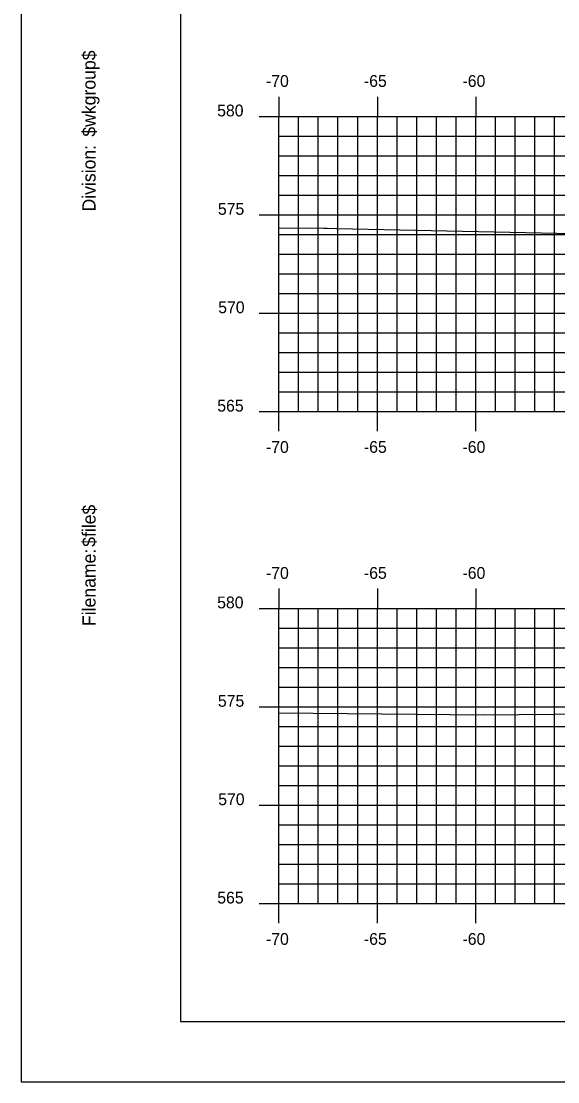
# Model space of a CAD drawing. Extents: x 1048109 to 1048279, y 781630 to 781740.
# Drawn here: x 1048108.6 to 1048135.9, y 781630.1 to 781684 of the extents above; entities that cross this region are included whole.
import ezdxf

# ---------------------------------------------------------------- set-up
doc = ezdxf.new("R2010")
doc.units = 0
for name, color, linetype in [('Default', 7, 'Continuous'), ('H_V ANNOTATION', 7, 'Continuous'), ('MAJOR', 7, 'Continuous'), ('MINOR', 7, 'Continuous'), ('S_Roadway_Centerline', 7, 'Continuous')]:
    doc.layers.add(name, color=color, linetype=linetype)

msp = doc.modelspace()

# ---------------------------------------------------------------- linework, layer by layer
at = {"layer": 'Default'}
for p, q in [((1048116.734, 781738.195), (1048116.734, 781633.195)), ((1048116.734, 781633.195), (1048276.734, 781633.195))]:
    msp.add_line(p, q, dxfattribs=at)
msp.add_lwpolyline([(1048108.64, 781630.136), (1048278.64, 781630.136), (1048278.64, 781740.136), (1048108.64, 781740.136)], close=True, dxfattribs=at)
at = {"layer": 'MAJOR'}
for p, q in [((1048121.733, 781680.197), (1048121.733, 781679.195)), ((1048121.733, 781680.197), (1048121.733, 781679.195)), ((1048126.733, 781680.197), (1048126.733, 781679.195)), ((1048126.733, 781680.197), (1048126.733, 781679.195)), ((1048131.733, 781680.197), (1048131.733, 781679.195)), ((1048131.733, 781680.197), (1048131.733, 781679.195)), ((1048120.731, 781679.195), (1048121.733, 781679.195)), ((1048120.731, 781679.195), (1048121.733, 781679.195)), ((1048121.733, 781679.195), (1048261.733, 781679.195)), ((1048121.733, 781664.195), (1048121.733, 781679.195)), ((1048121.733, 781664.195), (1048121.733, 781679.195)), ((1048121.733, 781679.195), (1048261.733, 781679.195)), ((1048121.733, 781679.195), (1048261.733, 781679.195)), ((1048121.733, 781664.195), (1048121.733, 781679.195)), ((1048121.733, 781664.195), (1048121.733, 781679.195)), ((1048121.733, 781679.195), (1048261.733, 781679.195)), ((1048126.733, 781664.195), (1048126.733, 781679.195)), ((1048126.733, 781664.195), (1048126.733, 781679.195)), ((1048131.733, 781664.195), (1048131.733, 781679.195)), ((1048131.733, 781664.195), (1048131.733, 781679.195)), ((1048120.731, 781674.195), (1048121.733, 781674.195)), ((1048120.731, 781674.195), (1048121.733, 781674.195)), ((1048121.733, 781674.195), (1048261.733, 781674.195)), ((1048121.733, 781674.195), (1048261.733, 781674.195)), ((1048120.731, 781669.195), (1048121.733, 781669.195)), ((1048120.731, 781669.195), (1048121.733, 781669.195)), ((1048121.733, 781669.195), (1048261.733, 781669.195)), ((1048121.733, 781669.195), (1048261.733, 781669.195)), ((1048120.731, 781664.195), (1048121.733, 781664.195)), ((1048120.731, 781664.195), (1048121.733, 781664.195)), ((1048121.733, 781664.195), (1048261.733, 781664.195)), ((1048121.733, 781664.195), (1048261.733, 781664.195)), ((1048121.733, 781663.193), (1048121.733, 781664.195)), ((1048121.733, 781664.195), (1048261.733, 781664.195)), ((1048121.733, 781664.195), (1048261.733, 781664.195)), ((1048121.733, 781663.193), (1048121.733, 781664.195)), ((1048126.733, 781663.193), (1048126.733, 781664.195)), ((1048126.733, 781663.193), (1048126.733, 781664.195)), ((1048131.733, 781663.193), (1048131.733, 781664.195)), ((1048131.733, 781663.193), (1048131.733, 781664.195)), ((1048121.733, 781655.197), (1048121.733, 781654.195)), ((1048121.733, 781655.197), (1048121.733, 781654.195)), ((1048126.733, 781655.197), (1048126.733, 781654.195)), ((1048126.733, 781655.197), (1048126.733, 781654.195)), ((1048131.733, 781655.197), (1048131.733, 781654.195)), ((1048131.733, 781655.197), (1048131.733, 781654.195)), ((1048120.731, 781654.195), (1048121.733, 781654.195)), ((1048120.731, 781654.195), (1048121.733, 781654.195)), ((1048121.733, 781654.195), (1048261.733, 781654.195)), ((1048121.733, 781639.195), (1048121.733, 781654.195)), ((1048121.733, 781639.195), (1048121.733, 781654.195)), ((1048121.733, 781654.195), (1048261.733, 781654.195)), ((1048121.733, 781654.195), (1048261.733, 781654.195)), ((1048121.733, 781639.195), (1048121.733, 781654.195)), ((1048121.733, 781639.195), (1048121.733, 781654.195)), ((1048121.733, 781654.195), (1048261.733, 781654.195)), ((1048126.733, 781639.195), (1048126.733, 781654.195)), ((1048126.733, 781639.195), (1048126.733, 781654.195)), ((1048131.733, 781639.195), (1048131.733, 781654.195)), ((1048131.733, 781639.195), (1048131.733, 781654.195)), ((1048120.731, 781649.195), (1048121.733, 781649.195)), ((1048120.731, 781649.195), (1048121.733, 781649.195)), ((1048121.733, 781649.195), (1048261.733, 781649.195)), ((1048121.733, 781649.195), (1048261.733, 781649.195)), ((1048120.731, 781644.195), (1048121.733, 781644.195)), ((1048120.731, 781644.195), (1048121.733, 781644.195)), ((1048121.733, 781644.195), (1048261.733, 781644.195)), ((1048121.733, 781644.195), (1048261.733, 781644.195)), ((1048120.731, 781639.195), (1048121.733, 781639.195)), ((1048120.731, 781639.195), (1048121.733, 781639.195)), ((1048121.733, 781639.195), (1048261.733, 781639.195)), ((1048121.733, 781639.195), (1048261.733, 781639.195)), ((1048121.733, 781638.193), (1048121.733, 781639.195)), ((1048121.733, 781639.195), (1048261.733, 781639.195)), ((1048121.733, 781639.195), (1048261.733, 781639.195)), ((1048121.733, 781638.193), (1048121.733, 781639.195)), ((1048126.733, 781638.193), (1048126.733, 781639.195)), ((1048126.733, 781638.193), (1048126.733, 781639.195)), ((1048131.733, 781638.193), (1048131.733, 781639.195)), ((1048131.733, 781638.193), (1048131.733, 781639.195))]:
    msp.add_line(p, q, dxfattribs=at)
at = {"layer": 'MINOR'}
for p, q in [((1048122.733, 781664.195), (1048122.733, 781679.195)), ((1048122.733, 781664.195), (1048122.733, 781679.195)), ((1048123.733, 781664.195), (1048123.733, 781679.195)), ((1048123.733, 781664.195), (1048123.733, 781679.195)), ((1048124.733, 781664.195), (1048124.733, 781679.195)), ((1048124.733, 781664.195), (1048124.733, 781679.195)), ((1048125.733, 781664.195), (1048125.733, 781679.195)), ((1048125.733, 781664.195), (1048125.733, 781679.195)), ((1048127.733, 781664.195), (1048127.733, 781679.195)), ((1048127.733, 781664.195), (1048127.733, 781679.195)), ((1048128.733, 781664.195), (1048128.733, 781679.195)), ((1048128.733, 781664.195), (1048128.733, 781679.195)), ((1048129.733, 781664.195), (1048129.733, 781679.195)), ((1048129.733, 781664.195), (1048129.733, 781679.195)), ((1048130.733, 781664.195), (1048130.733, 781679.195)), ((1048130.733, 781664.195), (1048130.733, 781679.195)), ((1048132.733, 781664.195), (1048132.733, 781679.195)), ((1048132.733, 781664.195), (1048132.733, 781679.195)), ((1048133.733, 781664.195), (1048133.733, 781679.195)), ((1048133.733, 781664.195), (1048133.733, 781679.195)), ((1048134.733, 781664.195), (1048134.733, 781679.195)), ((1048134.733, 781664.195), (1048134.733, 781679.195)), ((1048135.733, 781664.195), (1048135.733, 781679.195)), ((1048135.733, 781664.195), (1048135.733, 781679.195)), ((1048121.733, 781678.195), (1048261.733, 781678.195)), ((1048121.733, 781678.195), (1048122.735, 781678.195)), ((1048121.733, 781678.195), (1048261.733, 781678.195)), ((1048121.733, 781678.195), (1048122.735, 781678.195)), ((1048121.733, 781677.195), (1048261.733, 781677.195)), ((1048121.733, 781677.195), (1048122.735, 781677.195)), ((1048121.733, 781677.195), (1048261.733, 781677.195)), ((1048121.733, 781677.195), (1048122.735, 781677.195)), ((1048121.733, 781676.195), (1048261.733, 781676.195)), ((1048121.733, 781676.195), (1048122.735, 781676.195)), ((1048121.733, 781676.195), (1048261.733, 781676.195)), ((1048121.733, 781676.195), (1048122.735, 781676.195)), ((1048121.733, 781675.195), (1048261.733, 781675.195)), ((1048121.733, 781675.195), (1048122.735, 781675.195)), ((1048121.733, 781675.195), (1048261.733, 781675.195)), ((1048121.733, 781675.195), (1048122.735, 781675.195)), ((1048121.733, 781673.195), (1048261.733, 781673.195)), ((1048121.733, 781673.195), (1048122.735, 781673.195)), ((1048121.733, 781673.195), (1048261.733, 781673.195)), ((1048121.733, 781673.195), (1048122.735, 781673.195)), ((1048121.733, 781672.195), (1048261.733, 781672.195)), ((1048121.733, 781672.195), (1048122.735, 781672.195)), ((1048121.733, 781672.195), (1048261.733, 781672.195)), ((1048121.733, 781672.195), (1048122.735, 781672.195)), ((1048121.733, 781671.195), (1048261.733, 781671.195)), ((1048121.733, 781671.195), (1048122.735, 781671.195)), ((1048121.733, 781671.195), (1048261.733, 781671.195)), ((1048121.733, 781671.195), (1048122.735, 781671.195)), ((1048121.733, 781670.195), (1048261.733, 781670.195)), ((1048121.733, 781670.195), (1048122.735, 781670.195)), ((1048121.733, 781670.195), (1048261.733, 781670.195)), ((1048121.733, 781670.195), (1048122.735, 781670.195)), ((1048121.733, 781668.195), (1048261.733, 781668.195)), ((1048121.733, 781668.195), (1048122.735, 781668.195)), ((1048121.733, 781668.195), (1048261.733, 781668.195)), ((1048121.733, 781668.195), (1048122.735, 781668.195)), ((1048121.733, 781667.195), (1048261.733, 781667.195)), ((1048121.733, 781667.195), (1048122.735, 781667.195)), ((1048121.733, 781667.195), (1048261.733, 781667.195)), ((1048121.733, 781667.195), (1048122.735, 781667.195)), ((1048121.733, 781666.195), (1048261.733, 781666.195)), ((1048121.733, 781666.195), (1048122.735, 781666.195)), ((1048121.733, 781666.195), (1048261.733, 781666.195)), ((1048121.733, 781666.195), (1048122.735, 781666.195)), ((1048121.733, 781665.195), (1048261.733, 781665.195)), ((1048121.733, 781665.195), (1048122.735, 781665.195)), ((1048121.733, 781665.195), (1048261.733, 781665.195)), ((1048121.733, 781665.195), (1048122.735, 781665.195)), ((1048122.733, 781639.195), (1048122.733, 781654.195)), ((1048122.733, 781639.195), (1048122.733, 781654.195)), ((1048123.733, 781639.195), (1048123.733, 781654.195)), ((1048123.733, 781639.195), (1048123.733, 781654.195)), ((1048124.733, 781639.195), (1048124.733, 781654.195)), ((1048124.733, 781639.195), (1048124.733, 781654.195)), ((1048125.733, 781639.195), (1048125.733, 781654.195)), ((1048125.733, 781639.195), (1048125.733, 781654.195)), ((1048127.733, 781639.195), (1048127.733, 781654.195)), ((1048127.733, 781639.195), (1048127.733, 781654.195)), ((1048128.733, 781639.195), (1048128.733, 781654.195)), ((1048128.733, 781639.195), (1048128.733, 781654.195)), ((1048129.733, 781639.195), (1048129.733, 781654.195)), ((1048129.733, 781639.195), (1048129.733, 781654.195)), ((1048130.733, 781639.195), (1048130.733, 781654.195)), ((1048130.733, 781639.195), (1048130.733, 781654.195)), ((1048132.733, 781639.195), (1048132.733, 781654.195)), ((1048132.733, 781639.195), (1048132.733, 781654.195)), ((1048133.733, 781639.195), (1048133.733, 781654.195)), ((1048133.733, 781639.195), (1048133.733, 781654.195)), ((1048134.733, 781639.195), (1048134.733, 781654.195)), ((1048134.733, 781639.195), (1048134.733, 781654.195)), ((1048135.733, 781639.195), (1048135.733, 781654.195)), ((1048135.733, 781639.195), (1048135.733, 781654.195)), ((1048121.733, 781653.195), (1048261.733, 781653.195)), ((1048121.733, 781653.195), (1048122.735, 781653.195)), ((1048121.733, 781653.195), (1048261.733, 781653.195)), ((1048121.733, 781653.195), (1048122.735, 781653.195)), ((1048121.733, 781652.195), (1048261.733, 781652.195)), ((1048121.733, 781652.195), (1048122.735, 781652.195)), ((1048121.733, 781652.195), (1048261.733, 781652.195)), ((1048121.733, 781652.195), (1048122.735, 781652.195)), ((1048121.733, 781651.195), (1048261.733, 781651.195)), ((1048121.733, 781651.195), (1048122.735, 781651.195)), ((1048121.733, 781651.195), (1048261.733, 781651.195)), ((1048121.733, 781651.195), (1048122.735, 781651.195)), ((1048121.733, 781650.195), (1048261.733, 781650.195)), ((1048121.733, 781650.195), (1048122.735, 781650.195)), ((1048121.733, 781650.195), (1048261.733, 781650.195)), ((1048121.733, 781650.195), (1048122.735, 781650.195)), ((1048121.733, 781648.195), (1048261.733, 781648.195)), ((1048121.733, 781648.195), (1048122.735, 781648.195)), ((1048121.733, 781648.195), (1048261.733, 781648.195)), ((1048121.733, 781648.195), (1048122.735, 781648.195)), ((1048121.733, 781647.195), (1048261.733, 781647.195)), ((1048121.733, 781647.195), (1048122.735, 781647.195)), ((1048121.733, 781647.195), (1048261.733, 781647.195)), ((1048121.733, 781647.195), (1048122.735, 781647.195)), ((1048121.733, 781646.195), (1048261.733, 781646.195)), ((1048121.733, 781646.195), (1048122.735, 781646.195)), ((1048121.733, 781646.195), (1048261.733, 781646.195)), ((1048121.733, 781646.195), (1048122.735, 781646.195)), ((1048121.733, 781645.195), (1048261.733, 781645.195)), ((1048121.733, 781645.195), (1048122.735, 781645.195)), ((1048121.733, 781645.195), (1048261.733, 781645.195)), ((1048121.733, 781645.195), (1048122.735, 781645.195)), ((1048121.733, 781643.195), (1048261.733, 781643.195)), ((1048121.733, 781643.195), (1048122.735, 781643.195)), ((1048121.733, 781643.195), (1048261.733, 781643.195)), ((1048121.733, 781643.195), (1048122.735, 781643.195)), ((1048121.733, 781642.195), (1048261.733, 781642.195)), ((1048121.733, 781642.195), (1048122.735, 781642.195)), ((1048121.733, 781642.195), (1048261.733, 781642.195)), ((1048121.733, 781642.195), (1048122.735, 781642.195)), ((1048121.733, 781641.195), (1048261.733, 781641.195)), ((1048121.733, 781641.195), (1048122.735, 781641.195)), ((1048121.733, 781641.195), (1048261.733, 781641.195)), ((1048121.733, 781641.195), (1048122.735, 781641.195)), ((1048121.733, 781640.195), (1048261.733, 781640.195)), ((1048121.733, 781640.195), (1048122.735, 781640.195)), ((1048121.733, 781640.195), (1048261.733, 781640.195)), ((1048121.733, 781640.195), (1048122.735, 781640.195))]:
    msp.add_line(p, q, dxfattribs=at)
at = {"layer": 'S_Roadway_Centerline'}
for points in [[(1048121.733, 781673.54), (1048124.021, 781673.514), (1048124.187, 781673.511), (1048124.678, 781673.501), (1048139.044, 781673.199), (1048143.343, 781673.047), (1048145.238, 781672.981), (1048146.562, 781672.932), (1048147.063, 781672.911), (1048147.593, 781672.904), (1048149.373, 781672.876), (1048151.33, 781672.839), (1048151.337, 781672.841), (1048165.263, 781672.839), (1048171.317, 781672.812), (1048173.701, 781672.801), (1048175.841, 781672.789), (1048179.234, 781672.771), (1048191.754, 781672.77), (1048192.331, 781672.75), (1048198.246, 781672.663), (1048213.646, 781672.566), (1048223.979, 781672.514)], [(1048121.733, 781648.883), (1048132.166, 781648.791), (1048158.795, 781649.038), (1048158.833, 781649.037), (1048162.032, 781649.025), (1048164.242, 781649.039), (1048164.257, 781649.038), (1048178.681, 781649.019), (1048190.522, 781649.013), (1048211.019, 781648.954), (1048233.093, 781648.88), (1048259.004, 781648.594), (1048261.733, 781648.51)]]:
    msp.add_lwpolyline(points, dxfattribs=at)

# ---------------------------------------------------------------- texts
at = {"layer": 'Default'}
for s, p in [('$wkgroup$', (1048112.418, 781678.165)), ('Division:', (1048112.418, 781674.362)), ('$file$', (1048112.418, 781657.321)), ('Filename:', (1048112.418, 781653.294))]:
    msp.add_text(s, height=0.6696, rotation=90, dxfattribs=at).set_placement(p)
at = {"layer": 'H_V ANNOTATION'}
for s, p in [('-70', (1048121.075, 781680.695)), ('-65', (1048126.051, 781680.695)), ('-60', (1048131.059, 781680.695)), ('580', (1048118.595, 781679.195)), ('575', (1048118.633, 781674.195)), ('570', (1048118.649, 781669.195)), ('565', (1048118.601, 781664.195)), ('-70', (1048121.075, 781662.095)), ('-65', (1048126.051, 781662.095)), ('-60', (1048131.059, 781662.095)), ('-70', (1048121.075, 781655.695)), ('-65', (1048126.051, 781655.695)), ('-60', (1048131.059, 781655.695)), ('580', (1048118.595, 781654.195)), ('575', (1048118.633, 781649.195)), ('570', (1048118.649, 781644.195)), ('565', (1048118.601, 781639.195)), ('-70', (1048121.075, 781637.095)), ('-65', (1048126.051, 781637.095)), ('-60', (1048131.059, 781637.095))]:
    msp.add_text(s, height=0.6, dxfattribs=at).set_placement(p)
at = {"layer": 'MAJOR'}
for p in [(1048121.729, 781664.195), (1048121.729, 781664.195), (1048121.729, 781639.195), (1048121.729, 781639.195)]:
    msp.add_text('-', height=0.006, dxfattribs=at).set_placement(p)

doc.saveas('drawing.dxf')
